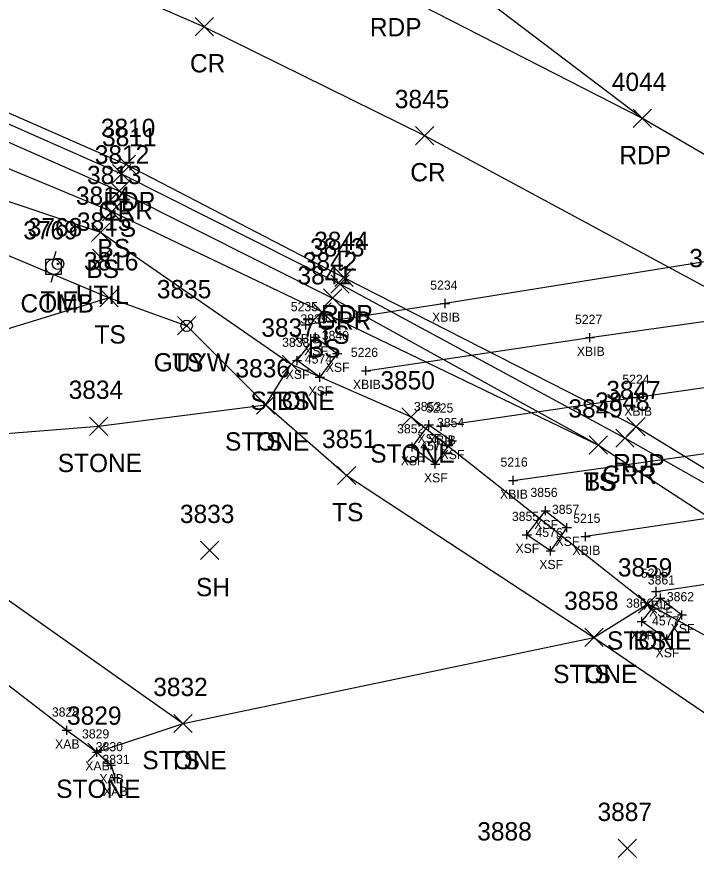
# Model space of a CAD drawing. Extents: x 1505656 to 1508446, y 700805 to 703031.
# Drawn here: x 1506970.4 to 1507044.6, y 701671.7 to 701763.7 of the extents above; entities that cross this region are included whole.
import ezdxf

# ---------------------------------------------------------------- set-up
doc = ezdxf.new("R2010")
doc.units = 0
for name, color, linetype in [('B_A', 7, 'Continuous'), ('B_I', 7, 'Continuous'), ('B_TIC', 7, 'Continuous'), ('BB', 7, 'Continuous'), ('BDEFAULT', 7, 'Continuous'), ('BSUBM', 7, 'Continuous'), ('C_A', 7, 'Continuous'), ('C_I', 7, 'Continuous'), ('CBP', 7, 'Continuous'), ('L_A', 7, 'Continuous'), ('L_I', 7, 'Continuous'), ('L_TIC', 7, 'Continuous'), ('LASF', 7, 'Continuous'), ('LELB', 7, 'Continuous'), ('P_A', 7, 'Continuous'), ('P_I', 7, 'Continuous'), ('P_TIC', 7, 'Continuous'), ('PET', 7, 'Continuous'), ('PRC', 7, 'Continuous'), ('R_A', 7, 'Continuous'), ('R_I', 7, 'Continuous'), ('R_TIC', 7, 'Continuous'), ('RGR', 7, 'Continuous'), ('U_A', 7, 'Continuous'), ('U_I', 7, 'Continuous'), ('UDEFAULT', 7, 'Continuous'), ('UP', 7, 'Continuous'), ('UPGW', 7, 'Continuous')]:
    doc.layers.add(name, color=color, linetype=linetype)

msp = doc.modelspace()

# ---------------------------------------------------------------- linework, layer by layer
at = {"layer": 'B_TIC'}
for p, q in [((1507017.187, 701732.352), (1507017.262, 701732.352)), ((1507001.945, 701730.001), (1507002.021, 701730.001)), ((1507003.01, 701728.663), (1507003.086, 701728.663)), ((1507033.01, 701728.611), (1507033.085, 701728.611)), ((1507005.38, 701726.862), (1507005.456, 701726.862)), ((1507001.001, 701726.102), (1507001.077, 701726.102)), ((1507008.536, 701725.001), (1507008.612, 701725.001)), ((1507003.484, 701724.281), (1507003.559, 701724.281)), ((1507038.183, 701722.066), (1507038.258, 701722.066)), ((1507015.403, 701719.082), (1507015.479, 701719.082)), ((1507016.738, 701718.919), (1507016.814, 701718.919)), ((1507017.928, 701717.328), (1507018.003, 701717.328)), ((1507013.566, 701716.65), (1507013.642, 701716.65)), ((1507016.108, 701714.791), (1507016.183, 701714.791)), ((1507024.608, 701713.008), (1507024.684, 701713.008)), ((1507028.164, 701709.689), (1507028.239, 701709.689)), ((1507026.116, 701707.073), (1507026.191, 701707.073)), ((1507030.492, 701707.841), (1507030.567, 701707.841)), ((1507032.531, 701706.864), (1507032.607, 701706.864)), ((1507028.715, 701705.312), (1507028.791, 701705.312)), ((1507040.253, 701700.866), (1507040.329, 701700.866)), ((1507040.705, 701700.124), (1507040.78, 701700.124)), ((1507043.069, 701698.296), (1507043.145, 701698.296)), ((1507038.668, 701697.587), (1507038.743, 701697.587)), ((1507041.428, 701695.658), (1507041.503, 701695.658)), ((1506975.835, 701685.682), (1506975.911, 701685.682)), ((1506979.136, 701683.292), (1506979.212, 701683.292)), ((1506980.678, 701681.89), (1506980.753, 701681.89)), ((1506981.08, 701680.511), (1506981.155, 701680.511))]:
    msp.add_line(p, q, dxfattribs=at)
for points in [[(1507017.183, 701731.852), (1507017.183, 701732.852)], [(1507016.683, 701732.352), (1507017.683, 701732.352)], [(1507001.442, 701730.001), (1507002.442, 701730.001)], [(1507001.942, 701729.501), (1507001.942, 701730.501)], [(1507003.007, 701728.163), (1507003.007, 701729.163)], [(1507033.006, 701728.111), (1507033.006, 701729.111)], [(1507002.507, 701728.663), (1507003.507, 701728.663)], [(1507032.506, 701728.611), (1507033.506, 701728.611)], [(1507005.377, 701726.362), (1507005.377, 701727.362)], [(1507000.998, 701725.602), (1507000.998, 701726.602)], [(1507004.877, 701726.862), (1507005.877, 701726.862)], [(1507000.498, 701726.102), (1507001.498, 701726.102)], [(1507008.533, 701724.501), (1507008.533, 701725.501)], [(1507003.48, 701723.781), (1507003.48, 701724.781)], [(1507008.033, 701725.001), (1507009.033, 701725.001)], [(1507002.98, 701724.281), (1507003.98, 701724.281)], [(1507037.679, 701722.066), (1507038.679, 701722.066)], [(1507038.179, 701721.566), (1507038.179, 701722.566)], [(1507014.9, 701719.082), (1507015.9, 701719.082)], [(1507015.4, 701718.582), (1507015.4, 701719.582)], [(1507016.735, 701718.419), (1507016.735, 701719.419)], [(1507016.235, 701718.919), (1507017.235, 701718.919)], [(1507013.563, 701716.15), (1507013.563, 701717.15)], [(1507017.424, 701717.328), (1507018.424, 701717.328)], [(1507017.924, 701716.828), (1507017.924, 701717.828)], [(1507013.063, 701716.65), (1507014.063, 701716.65)], [(1507016.104, 701714.291), (1507016.104, 701715.291)], [(1507015.604, 701714.791), (1507016.604, 701714.791)], [(1507024.605, 701712.508), (1507024.605, 701713.508)], [(1507024.105, 701713.008), (1507025.105, 701713.008)], [(1507028.161, 701709.189), (1507028.161, 701710.189)], [(1507027.661, 701709.689), (1507028.661, 701709.689)], [(1507030.488, 701707.34), (1507030.488, 701708.341)], [(1507025.612, 701707.073), (1507026.612, 701707.073)], [(1507026.112, 701706.573), (1507026.112, 701707.573)], [(1507029.988, 701707.841), (1507030.988, 701707.841)], [(1507032.528, 701706.364), (1507032.528, 701707.364)], [(1507032.028, 701706.864), (1507033.028, 701706.864)], [(1507028.212, 701705.312), (1507029.212, 701705.312)], [(1507028.712, 701704.812), (1507028.712, 701705.812)], [(1507039.75, 701700.866), (1507040.75, 701700.866)], [(1507040.25, 701700.366), (1507040.25, 701701.366)], [(1507040.701, 701699.624), (1507040.701, 701700.624)], [(1507040.201, 701700.124), (1507041.201, 701700.124)], [(1507043.066, 701697.796), (1507043.066, 701698.796)], [(1507038.664, 701697.087), (1507038.664, 701698.087)], [(1507042.566, 701698.296), (1507043.566, 701698.296)], [(1507038.164, 701697.587), (1507039.164, 701697.587)], [(1507041.424, 701695.158), (1507041.424, 701696.158)], [(1507040.924, 701695.658), (1507041.924, 701695.658)], [(1506975.832, 701685.182), (1506975.832, 701686.182)], [(1506975.332, 701685.682), (1506976.332, 701685.682)], [(1506978.633, 701683.292), (1506979.633, 701683.292)], [(1506979.133, 701682.792), (1506979.133, 701683.792)], [(1506980.674, 701681.39), (1506980.674, 701682.39)], [(1506980.174, 701681.89), (1506981.174, 701681.89)], [(1506980.576, 701680.511), (1506981.576, 701680.511)], [(1506981.076, 701680.011), (1506981.076, 701681.011)]]:
    msp.add_lwpolyline(points, dxfattribs=at)
at = {"layer": 'BB'}
for points in [[(1507092.392, 701744.394), (1507070.686, 701740.9), (1507049.159, 701737.473), (1507017.183, 701732.352), (1507001.942, 701730.001)], [(1507008.533, 701725.001), (1507033.006, 701728.611), (1507057.548, 701732.084), (1507079.477, 701735.426), (1507097.734, 701737.947)], [(1507108.232, 701732.089), (1507088.46, 701729.428), (1507061.411, 701725.439), (1507038.179, 701722.066), (1507016.735, 701718.919)], [(1507024.605, 701713.008), (1507048.7, 701716.392), (1507073.949, 701720.121), (1507094.598, 701723.028), (1507115.169, 701725.943)], [(1507124.099, 701719.631), (1507101.726, 701716.728), (1507083.677, 701714.234), (1507058.067, 701710.655), (1507032.528, 701706.864)], [(1507040.25, 701700.866), (1507063.71, 701704.361), (1507080.724, 701706.888), (1507092.161, 701708.296), (1507108.35, 701710.099), (1507130.317, 701713.378)]]:
    msp.add_lwpolyline(points, dxfattribs=at)
at = {"layer": 'BDEFAULT'}
for points in [[(1507000.998, 701726.102), (1507003.007, 701728.663), (1507005.377, 701726.862), (1507003.48, 701724.281)], [(1507003.48, 701724.281), (1507000.998, 701726.102)], [(1507013.563, 701716.65), (1507015.4, 701719.082), (1507017.924, 701717.328), (1507016.104, 701714.791)], [(1507016.104, 701714.791), (1507013.563, 701716.65)], [(1507026.112, 701707.073), (1507028.161, 701709.689), (1507030.488, 701707.841), (1507028.712, 701705.312)], [(1507028.712, 701705.312), (1507026.112, 701707.073)], [(1507038.664, 701697.587), (1507040.701, 701700.124), (1507043.066, 701698.296), (1507041.424, 701695.658)], [(1507041.424, 701695.658), (1507038.664, 701697.587)]]:
    msp.add_lwpolyline(points, dxfattribs=at)
at = {"layer": 'BSUBM'}
msp.add_lwpolyline([(1506933.462, 701719.329), (1506933.699, 701717.779), (1506937.831, 701714.659), (1506944.607, 701709.483), (1506952.561, 701703.359), (1506960.599, 701697.328), (1506968.511, 701691.304), (1506975.832, 701685.682), (1506979.133, 701683.292), (1506980.674, 701681.89), (1506981.076, 701680.511)], dxfattribs=at)
at = {"layer": 'CBP'}
for radius in [0.625, 0.0833]:
    msp.add_circle((1506974.874, 701736.686), radius, dxfattribs=at)
at = {"layer": 'L_TIC'}
for points in [[(1506980.588, 701743.638), (1506982.588, 701745.638)], [(1506982.588, 701743.638), (1506980.588, 701745.638)], [(1506979.741, 701741.4), (1506981.741, 701743.4)], [(1506981.741, 701741.4), (1506979.741, 701743.4)], [(1506978.529, 701739.136), (1506980.529, 701741.136)], [(1506980.529, 701739.136), (1506978.529, 701741.136)], [(1506979.453, 701731.965), (1506981.453, 701733.965)], [(1506981.453, 701731.965), (1506979.453, 701733.965)], [(1506979.453, 701731.965), (1506981.453, 701733.965)], [(1506981.453, 701731.965), (1506979.453, 701733.965)], [(1507003.89, 701731.933), (1507005.89, 701733.933)], [(1507005.89, 701731.933), (1507003.89, 701733.933)], [(1507002.738, 701730.435), (1507004.738, 701732.435)], [(1507004.738, 701730.435), (1507002.738, 701732.435)], [(1506987.936, 701728.914), (1506989.936, 701730.914)], [(1506989.936, 701728.914), (1506987.936, 701730.914)], [(1506999.357, 701724.713), (1507001.357, 701726.713)], [(1507001.357, 701724.713), (1506999.357, 701726.713)], [(1506999.357, 701724.713), (1507001.357, 701726.713)], [(1507001.357, 701724.713), (1506999.357, 701726.713)], [(1506996.581, 701720.265), (1506998.581, 701722.265)], [(1506998.581, 701720.265), (1506996.581, 701722.265)], [(1506996.581, 701720.265), (1506998.581, 701722.265)], [(1506998.581, 701720.265), (1506996.581, 701722.265)], [(1507012.458, 701718.951), (1507014.458, 701720.951)], [(1507014.458, 701718.951), (1507012.458, 701720.951)], [(1506978.301, 701717.917), (1506980.301, 701719.917)], [(1506980.301, 701717.917), (1506978.301, 701719.917)], [(1507032.925, 701715.874), (1507034.925, 701717.874)], [(1507034.925, 701715.874), (1507032.925, 701717.874)], [(1507032.925, 701715.874), (1507034.925, 701717.874)], [(1507034.925, 701715.874), (1507032.925, 701717.874)], [(1507005.421, 701712.54), (1507007.421, 701714.54)], [(1507007.421, 701712.54), (1507005.421, 701714.54)], [(1506990.459, 701704.345), (1506992.459, 701706.345)], [(1506992.459, 701704.345), (1506990.459, 701706.345)], [(1507038.326, 701698.504), (1507040.326, 701700.504)], [(1507040.326, 701698.504), (1507038.326, 701700.504)], [(1507038.326, 701698.504), (1507040.326, 701700.504)], [(1507040.326, 701698.504), (1507038.326, 701700.504)], [(1507038.326, 701698.504), (1507040.326, 701700.504)], [(1507040.326, 701698.504), (1507038.326, 701700.504)], [(1507032.447, 701694.844), (1507034.447, 701696.844)], [(1507034.447, 701694.844), (1507032.447, 701696.844)], [(1507032.447, 701694.844), (1507034.447, 701696.844)], [(1507034.447, 701694.844), (1507032.447, 701696.844)], [(1506987.545, 701685.429), (1506989.545, 701687.429)], [(1506989.545, 701685.429), (1506987.545, 701687.429)], [(1506987.545, 701685.429), (1506989.545, 701687.429)], [(1506989.545, 701685.429), (1506987.545, 701687.429)], [(1506978.133, 701682.292), (1506980.133, 701684.292)], [(1506980.133, 701682.292), (1506978.133, 701684.292)], [(1507036.096, 701671.771), (1507038.096, 701673.771)], [(1507038.096, 701671.771), (1507036.096, 701673.771)]]:
    msp.add_lwpolyline(points, dxfattribs=at)
at = {"layer": 'LASF'}
for points in [[(1506933.699, 701717.779), (1506946.347, 701716.317), (1506979.301, 701718.917), (1506997.581, 701721.265), (1507000.357, 701725.713), (1507013.458, 701719.951), (1507039.326, 701699.504)], [(1506979.133, 701683.292), (1506988.545, 701686.429), (1507033.447, 701695.844), (1507039.326, 701699.504)]]:
    msp.add_lwpolyline(points, dxfattribs=at)
at = {"layer": 'LELB'}
for points in [[(1506800.37, 701797.227), (1506837.502, 701789.661), (1506872.573, 701779.991), (1506888.275, 701777.134), (1506896.491, 701775.978), (1506915.536, 701769.579), (1506955.58, 701756.101), (1506981.588, 701744.638), (1507004.89, 701732.933), (1507033.925, 701716.874), (1507075.078, 701690.038), (1507096.481, 701678.331), (1507134.734, 701654.114), (1507144.566, 701644.084), (1507157.616, 701629.156), (1507171.153, 701621.359), (1507203.372, 701598.114), (1507252.669, 701568.12)], [(1506917.007, 701765.449), (1506930.841, 701759.918), (1506954.44, 701753.352), (1506980.741, 701742.4), (1507003.738, 701731.435), (1507033.925, 701716.874)], [(1506929.405, 701756.366), (1506952.542, 701749.146), (1506979.529, 701740.136), (1507000.357, 701725.713)], [(1506928.857, 701753.067), (1506952.265, 701744.827), (1506980.453, 701732.965), (1506988.936, 701729.914), (1506997.581, 701721.265), (1507006.421, 701713.54), (1507033.447, 701695.844), (1507060.159, 701677.649), (1507085.773, 701663.346), (1507095.509, 701656.181)], [(1506980.453, 701732.965), (1506966.091, 701728.551), (1506944.196, 701723.385), (1506946.347, 701716.317), (1506963.961, 701703.788), (1506988.545, 701686.429)], [(1507039.326, 701699.504), (1507069.563, 701682.859), (1507089.894, 701670.006), (1507105.384, 701659.103)]]:
    msp.add_lwpolyline(points, dxfattribs=at)
at = {"layer": 'P_TIC'}
for points in [[(1506989.861, 701761.611), (1506991.861, 701763.611)], [(1506991.861, 701761.611), (1506989.861, 701763.611)], [(1507037.741, 701751.578), (1507039.741, 701753.578)], [(1507039.741, 701751.578), (1507037.741, 701753.578)], [(1507037.741, 701751.578), (1507039.741, 701753.578)], [(1507039.741, 701751.578), (1507037.741, 701753.578)], [(1507013.943, 701749.701), (1507015.943, 701751.701)], [(1507015.943, 701749.701), (1507013.943, 701751.701)], [(1506981.339, 701746.546), (1506983.339, 701748.546)], [(1506983.339, 701746.546), (1506981.339, 701748.546)], [(1507005.129, 701734.192), (1507007.129, 701736.192)], [(1507007.129, 701734.192), (1507005.129, 701736.192)], [(1507037.054, 701717.888), (1507039.054, 701719.888)], [(1507039.054, 701717.888), (1507037.054, 701719.888)]]:
    msp.add_lwpolyline(points, dxfattribs=at)
at = {"layer": 'PET'}
for points in [[(1507038.741, 701752.578), (1507014.862, 701770.715), (1506991.52, 701787.642), (1506981.363, 701794.227), (1506979.484, 701796.169), (1506973.183, 701801.367), (1506953.336, 701817.697), (1506940.173, 701829.703), (1506923.68, 701848.647), (1506908.362, 701872.249), (1506900.075, 701892.245), (1506893.846, 701912.079), (1506888.565, 701936.911), (1506887.764, 701946.067), (1506883.682, 701946.308)], [(1507378.585, 701528.733), (1507351.162, 701547.398), (1507314.879, 701572.263), (1507294.108, 701586.218), (1507256.279, 701612.267), (1507223.676, 701635.256), (1507191.525, 701659.043), (1507185.406, 701663.235), (1507156.106, 701681.545), (1507130.98, 701696.871), (1507096.155, 701719.908), (1507064.317, 701737.661), (1507038.741, 701752.578), (1507011.468, 701766.553), (1506986.915, 701777.549), (1506973.482, 701783.538), (1506938.472, 701797.086), (1506905.532, 701808.927), (1506877.578, 701817.043), (1506846.407, 701824.784), (1506827.397, 701828.82), (1506804.261, 701834.037), (1506782.212, 701837.879), (1506762.062, 701842.486)], [(1506801.05, 701801.395), (1506837.914, 701794.781), (1506879.073, 701785.392), (1506932.665, 701768.553), (1506956.683, 701758.8), (1506982.339, 701747.546), (1507006.129, 701735.192), (1507038.054, 701718.888), (1507049.896, 701711.662), (1507082.097, 701692.151), (1507099.132, 701680.839), (1507137.172, 701655.934), (1507148.983, 701647.969), (1507175.665, 701630.096), (1507210.004, 701607.346), (1507255.636, 701576.087)]]:
    msp.add_lwpolyline(points, dxfattribs=at)
at = {"layer": 'PRC'}
msp.add_lwpolyline([(1506542.563, 701811.258), (1506583.456, 701819.163), (1506611.915, 701823.044), (1506639.632, 701825.584), (1506682.361, 701827.381), (1506720.712, 701826.613), (1506759.113, 701825.094), (1506802.873, 701820.093), (1506841.694, 701813.277), (1506883.623, 701802.647), (1506939.518, 701784.018), (1506961.706, 701775.319), (1506990.861, 701762.611), (1507014.943, 701750.701), (1507047.18, 701733.313), (1507059.635, 701726.12), (1507093.714, 701705.344), (1507109.291, 701695.301), (1507149.331, 701669.456), (1507158.784, 701662.649), (1507185.012, 701645.13), (1507221.624, 701620.548), (1507265.062, 701591.23)], dxfattribs=at)
at = {"layer": 'R_TIC'}
for points in [[(1506980.816, 701745.54), (1506982.816, 701747.54)], [(1506982.816, 701745.54), (1506980.816, 701747.54)], [(1507004.678, 701733.484), (1507006.678, 701735.484)], [(1507006.678, 701733.484), (1507004.678, 701735.484)], [(1507035.84, 701716.623), (1507037.84, 701718.623)], [(1507037.84, 701716.623), (1507035.84, 701718.623)]]:
    msp.add_lwpolyline(points, dxfattribs=at)
at = {"layer": 'RGR'}
msp.add_lwpolyline([(1506551.24, 701797.839), (1506571.594, 701801.361), (1506614.429, 701805.89), (1506642.246, 701806.936), (1506685.176, 701808.53), (1506719.99, 701808.29), (1506758.763, 701805.832), (1506800.88, 701800.842), (1506837.733, 701793.829), (1506878.725, 701783.931), (1506932.115, 701767.5), (1506956.302, 701757.767), (1506981.816, 701746.54), (1507005.678, 701734.484), (1507036.84, 701717.623), (1507049.284, 701710.579), (1507081.069, 701691.673), (1507098.391, 701680.194), (1507136.763, 701655.283), (1507148.635, 701647.399), (1507175.486, 701629.55), (1507209.72, 701606.655), (1507254.701, 701574.394), (1507264.029, 701565.842)], dxfattribs=at)
at = {"layer": 'UDEFAULT'}
for points in [[(1506978.638, 701736.301), (1506980.638, 701738.301)], [(1506980.638, 701736.301), (1506978.638, 701738.301)]]:
    msp.add_lwpolyline(points, dxfattribs=at)
at = {"layer": 'UP'}
for p, q in [((1506974.638, 701738.028), (1506974.388, 701737.195)), ((1506973.555, 701735.528), (1506973.555, 701737.195)), ((1506973.555, 701737.195), (1506975.222, 701737.195)), ((1506975.222, 701737.195), (1506975.222, 701735.528)), ((1506975.222, 701735.528), (1506973.555, 701735.528)), ((1506974.138, 701734.695), (1506974.388, 701735.528)), ((1506974.388, 701736.361), (1506974.388, 701736.361))]:
    msp.add_line(p, q, dxfattribs=at)
msp.add_circle((1506974.388, 701736.361), 0.833, dxfattribs=at)
at = {"layer": 'UPGW'}
for radius in [0.625, 0.0833]:
    msp.add_circle((1506988.936, 701729.914), radius, dxfattribs=at)

# ---------------------------------------------------------------- texts
at = {"layer": 'B_A'}
for s, p in [('XBIB', (1507015.754, 701730.352)), ('XBIB', (1507000.512, 701728.001)), ('XSF', (1507001.767, 701726.663)), ('XBIB', (1507031.577, 701726.611)), ('XSF', (1507004.136, 701724.862)), ('XSF', (1506999.758, 701724.102)), ('XBIB', (1507007.103, 701723.001)), ('XSF', (1507002.24, 701722.281)), ('XBIB', (1507036.75, 701720.066)), ('XSF', (1507014.16, 701717.082)), ('XBIB', (1507015.306, 701716.919)), ('XSF', (1507016.684, 701715.328)), ('XSF', (1507012.323, 701714.65)), ('XSF', (1507014.864, 701712.791)), ('XBIB', (1507023.176, 701711.008)), ('XSF', (1507026.92, 701707.689)), ('XSF', (1507024.872, 701705.073)), ('XSF', (1507029.248, 701705.841)), ('XBIB', (1507031.098, 701704.864)), ('XSF', (1507027.472, 701703.312)), ('XBIB', (1507038.821, 701698.866)), ('XSF', (1507039.461, 701698.124)), ('XSF', (1507041.825, 701696.296)), ('XSF', (1507037.424, 701695.587)), ('XSF', (1507040.184, 701693.658)), ('XAB', (1506974.552, 701683.682)), ('XAB', (1506977.853, 701681.292)), ('XAB', (1506979.395, 701679.89)), ('XAB', (1506979.797, 701678.511))]:
    msp.add_text(s, height=1, dxfattribs=at).set_placement(p)
at = {"layer": 'B_I'}
for s, p in [('5234', (1507015.554, 701733.852)), ('5235', (1507000.312, 701731.501)), ('3839', (1507001.373, 701730.163)), ('5227', (1507031.376, 701730.111)), ('3840', (1507003.703, 701728.362)), ('3838', (1506999.368, 701727.602)), ('5226', (1507006.875, 701726.501)), ('4574', (1507001.85, 701725.781)), ('5224', (1507036.549, 701723.566)), ('3853', (1507013.77, 701720.582)), ('5225', (1507015.105, 701720.419)), ('3852', (1507011.933, 701718.15)), ('3854', (1507016.294, 701718.828)), ('4575', (1507014.474, 701716.291)), ('5216', (1507023.231, 701714.508)), ('3856', (1507026.503, 701711.189)), ('3857', (1507028.858, 701709.341)), ('3855', (1507024.482, 701708.573)), ('5215', (1507031.181, 701708.364)), ('4576', (1507027.055, 701706.812)), ('5205', (1507038.581, 701702.366)), ('3861', (1507039.331, 701701.624)), ('3862', (1507041.412, 701699.796)), ('3860', (1507036.968, 701699.087)), ('4577', (1507039.794, 701697.158)), ('3828', (1506974.202, 701687.182)), ('3829', (1506977.499, 701684.792)), ('3830', (1506979.001, 701683.39)), ('3831', (1506979.73, 701682.011))]:
    msp.add_text(s, height=1, dxfattribs=at).set_placement(p)
at = {"layer": 'C_A'}
msp.add_text('TIE', height=2, dxfattribs=at).set_placement((1506972.953, 701731.686))
at = {"layer": 'C_I'}
msp.add_text('3768', height=2, dxfattribs=at).set_placement((1506971.567, 701739.686))
at = {"layer": 'L_A'}
for s, p in [('TS', (1506979.997, 701739.638)), ('BS', (1506979.182, 701737.4)), ('BS', (1506977.97, 701735.136)), ('TS', (1506978.863, 701727.965)), ('TS', (1506978.863, 701727.965)), ('TS', (1507003.3, 701727.933)), ('BS', (1507002.179, 701726.435)), ('TS', (1506987.346, 701724.914)), ('STONE', (1506995.901, 701720.713)), ('BS', (1506998.798, 701720.713)), ('STONE', (1506993.125, 701716.265)), ('TS', (1506995.991, 701716.265)), ('STONE', (1507009.001, 701714.951)), ('STONE', (1506974.844, 701713.917)), ('TS', (1507032.335, 701711.874)), ('BS', (1507032.366, 701711.874)), ('TS', (1507004.831, 701708.54)), ('SH', (1506989.948, 701700.345)), ('STONE', (1507034.869, 701694.504)), ('STONE', (1507034.869, 701694.504)), ('BS', (1507037.767, 701694.504)), ('STONE', (1507028.99, 701690.844)), ('TS', (1507031.856, 701690.844)), ('STONE', (1506984.089, 701681.429)), ('TS', (1506986.955, 701681.429)), ('STONE', (1506974.676, 701678.292))]:
    msp.add_text(s, height=2, dxfattribs=at).set_placement(p)
at = {"layer": 'L_I'}
for s, p in [('3812', (1506978.895, 701747.638)), ('3813', (1506978.049, 701745.4)), ('3814', (1506976.836, 701743.136)), ('3816', (1506977.705, 701735.965)), ('3816', (1506977.705, 701735.965)), ('3842', (1507001.63, 701735.933)), ('3841', (1507001.046, 701734.435)), ('3835', (1506985.676, 701732.914)), ('3837', (1506997.097, 701728.713)), ('3837', (1506997.097, 701728.713)), ('3836', (1506994.266, 701724.265)), ('3836', (1506994.266, 701724.265)), ('3850', (1507010.112, 701722.951)), ('3834', (1506976.041, 701721.917)), ('3849', (1507030.657, 701719.874)), ('3849', (1507030.657, 701719.874)), ('3851', (1507003.728, 701716.54)), ('3833', (1506988.2, 701708.345)), ('3859', (1507036.058, 701702.504)), ('3859', (1507036.058, 701702.504)), ('3859', (1507036.058, 701702.504)), ('3858', (1507030.187, 701698.844)), ('3858', (1507030.187, 701698.844)), ('3832', (1506985.285, 701689.429)), ('3832', (1506985.285, 701689.429)), ('3829', (1506975.865, 701686.292)), ('3887', (1507033.836, 701675.771)), ('3888', (1507020.696, 701673.639))]:
    msp.add_text(s, height=2, dxfattribs=at).set_placement(p)
at = {"layer": 'P_A'}
for s, p in [('RDP', (1507008.956, 701761.553)), ('CR', (1506989.294, 701757.611)), ('RDP', (1507036.229, 701747.578)), ('RDP', (1507036.229, 701747.578)), ('CR', (1507013.376, 701745.701)), ('RDP', (1506979.827, 701742.546)), ('RDP', (1507003.618, 701730.192)), ('RDP', (1507035.542, 701713.888))]:
    msp.add_text(s, height=2, dxfattribs=at).set_placement(p)
at = {"layer": 'P_I'}
for s, p in [('4044', (1507035.403, 701755.578)), ('4044', (1507035.403, 701755.578)), ('3845', (1507011.683, 701753.701)), ('3810', (1506979.559, 701750.546)), ('3844', (1507002.87, 701738.192)), ('3846', (1507043.865, 701736.313)), ('3847', (1507034.794, 701721.888))]:
    msp.add_text(s, height=2, dxfattribs=at).set_placement(p)
at = {"layer": 'R_A'}
for p in [(1506979.304, 701741.54), (1507003.166, 701729.484), (1507034.328, 701712.623)]:
    msp.add_text('GRR', height=2, dxfattribs=at).set_placement(p)
at = {"layer": 'R_I'}
for s, p in [('3811', (1506979.69, 701749.54)), ('3843', (1507002.418, 701737.484)), ('3848', (1507033.58, 701720.623))]:
    msp.add_text(s, height=2, dxfattribs=at).set_placement(p)
at = {"layer": 'U_A'}
for s, p in [('UTIL', (1506976.803, 701732.301)), ('COMB', (1506970.774, 701731.361)), ('GUYW', (1506985.33, 701724.914))]:
    msp.add_text(s, height=2, dxfattribs=at).set_placement(p)
at = {"layer": 'U_I'}
for s, p in [('3815', (1506976.945, 701740.301)), ('3769', (1506971.074, 701739.361)), ('3835', (1506985.676, 701732.914))]:
    msp.add_text(s, height=2, dxfattribs=at).set_placement(p)

doc.saveas('drawing.dxf')
